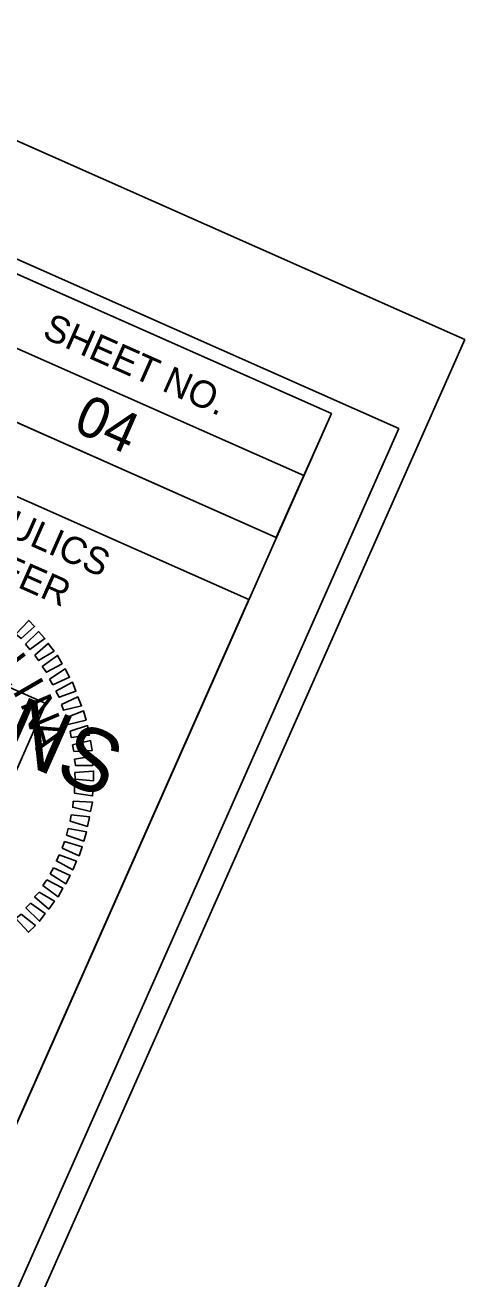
# Model space of a CAD drawing. Extents: x 1637682 to 2864602, y 842496 to 973236.
# Drawn here: x 1639584 to 1639665.2, y 843323.7 to 843555.1 of the extents above; entities that cross this region are included whole.
import ezdxf

# ---------------------------------------------------------------- set-up
doc = ezdxf.new("R2010")
doc.units = 0
for name, color, linetype in [('Old_Level_2', 7, 'Continuous'), ('Sheet Data Field CELL', 7, 'Continuous'), ('Sheet Plan CELL', 7, 'Continuous'), ('Sheet Plot Border Inside CELL', 7, 'Continuous'), ('Sheet Plot Border Outside CELL', 7, 'Continuous'), ('Sheet Sticker Incomplete CELL', 7, 'Continuous')]:
    doc.layers.add(name, color=color, linetype=linetype)

msp = doc.modelspace()

# ---------------------------------------------------------------- linework, layer by layer
at = {"layer": 'Old_Level_2'}
for points in [[(1639582.28, 843442.66), (1639584.67, 843445.23), (1639585.77, 843444.08), (1639583.25, 843441.86)], [(1639584.06, 843440.83), (1639586.47, 843443.17), (1639587.67, 843441.86), (1639584.9, 843439.85)], [(1639585.81, 843438.79), (1639588.27, 843440.98), (1639589.37, 843439.55), (1639586.48, 843437.82)], [(1639587.14, 843436.69), (1639590, 843438.77), (1639590.83, 843437.23), (1639587.95, 843435.67)], [(1639588.5, 843434.41), (1639591.4, 843436.31), (1639592.21, 843434.72), (1639589.13, 843433.35)], [(1639589.7, 843432.15), (1639592.73, 843433.82), (1639593.4, 843432.17), (1639590.31, 843431.04)], [(1639590.72, 843429.73), (1639593.75, 843431.12), (1639594.42, 843429.47), (1639591.12, 843428.65)], [(1639591.67, 843427.28), (1639594.81, 843428.51), (1639595.27, 843426.79), (1639591.94, 843426.03)], [(1639592.32, 843424.79), (1639595.54, 843425.82), (1639595.86, 843424.04), (1639592.52, 843423.63)], [(1639592.74, 843422.29), (1639596.07, 843423.04), (1639596.37, 843421.21), (1639593.01, 843421.04)], [(1639593.1, 843419.64), (1639596.51, 843420.19), (1639596.5, 843418.43), (1639593.29, 843418.48)], [(1639593.19, 843417.16), (1639596.64, 843417.41), (1639596.61, 843415.6), (1639593.22, 843415.9)], [(1639593.1, 843414.53), (1639596.56, 843414.54), (1639596.46, 843412.83), (1639593.15, 843413.32)], [(1639592.89, 843411.9), (1639596.44, 843411.7), (1639596.06, 843409.99), (1639592.8, 843410.74)], [(1639592.49, 843409.34), (1639595.91, 843408.97), (1639595.51, 843407.21), (1639592.35, 843408.21)], [(1639591.95, 843406.84), (1639595.36, 843406.2), (1639594.82, 843404.5), (1639591.65, 843405.61)], [(1639591.26, 843404.41), (1639594.55, 843403.47), (1639593.96, 843401.79), (1639590.87, 843403.21)], [(1639590.29, 843401.98), (1639593.48, 843400.8), (1639592.79, 843399.17), (1639589.8, 843400.83)], [(1639589.22, 843399.59), (1639592.31, 843398.17), (1639591.55, 843396.63), (1639588.64, 843398.48)], [(1639588.01, 843397.38), (1639590.97, 843395.79), (1639590.08, 843394.24), (1639587.28, 843396.33)], [(1639584.98, 843393.04), (1639587.7, 843391.16), (1639586.69, 843389.71), (1639584.17, 843392.2)], [(1639586.58, 843395.09), (1639589.41, 843393.44), (1639588.38, 843391.95), (1639585.77, 843394.24)], [(1639583.28, 843391.04), (1639585.9, 843388.91), (1639584.64, 843387.68), (1639582.32, 843390.25)]]:
    msp.add_lwpolyline(points, close=True, dxfattribs=at)
at = {"layer": 'Sheet Plan CELL'}
for p, q in [((1639452.57, 843553.04), (1639635.44, 843471.94)), ((1639447.5, 843541.57), (1639630.37, 843460.51)), ((1639447.5, 843541.57), (1639630.37, 843460.51))]:
    msp.add_line(p, q, dxfattribs=at)
for points in [[(1639640.56, 843483.39), (1638269.28, 844091.43), (1637843.67, 843131.56), (1639214.92, 842523.53)], [(1639457.67, 843564.51), (1639640.56, 843483.39), (1639630.37, 843460.51), (1639447.5, 843541.57)], [(1639533.9, 843489.6), (1639625.31, 843449.08), (1639579.71, 843346.22), (1639488.29, 843386.75)]]:
    msp.add_lwpolyline(points, close=True, dxfattribs=at)
at = {"layer": 'Sheet Plot Border Inside CELL'}
msp.add_lwpolyline([(1637702.34, 843191.48), (1639225.33, 842516.19), (1639652.97, 843480.61), (1638129.98, 844155.92)], close=True, dxfattribs=at)
at = {"layer": 'Sheet Plot Border Outside CELL'}
msp.add_lwpolyline([(1637682.35, 843178.46), (1639221.34, 842496.06), (1639665.19, 843497.07), (1638126.2, 844179.47)], close=True, dxfattribs=at)
msp.add_lwpolyline([(1637682.35, 843178.46), (1639221.34, 842496.06), (1639665.19, 843497.07), (1638126.2, 844179.47)], close=True, dxfattribs=at)
at = {"layer": 'Sheet Sticker Incomplete CELL'}
msp.add_lwpolyline([(1639443.9, 843467.97), (1639453.43, 843489.46), (1639587.81, 843429.87), (1639578.29, 843408.39)], close=True, dxfattribs=at)

# ---------------------------------------------------------------- texts
at = {"layer": 'Old_Level_2'}
for s, rotation, p in [('L', 307.308, (1639578.61, 843436.27)), ('I', 300.1073, (1639581.54, 843432.31)), ('N', 292.906, (1639582.98, 843429.94)), ('A', 285.7043, (1639584.62, 843425.9))]:
    msp.add_text(s, height=5.9, rotation=rotation, dxfattribs=at).set_placement(p)
at = {"layer": 'Sheet Data Field CELL'}
msp.add_text('04', height=7.5, rotation=336.0871, dxfattribs=at).set_placement((1639592.59, 843480.32))
at = {"layer": 'Sheet Plan CELL'}
for s, p in [('SHEET NO.', (1639586.97, 843497.5)), ('HYDRAULICS', (1639558.8, 843470.6)), ('ENGINEER', (1639559.01, 843461.8))]:
    msp.add_text(s, height=5, rotation=336.0871, dxfattribs=at).set_placement(p)
at = {"layer": 'Sheet Sticker Incomplete CELL'}
msp.add_text('INCOMPLETE PLANS', height=11.52, rotation=336.0871, dxfattribs=at).set_placement((1639456.83, 843475.04))

doc.saveas('drawing.dxf')
